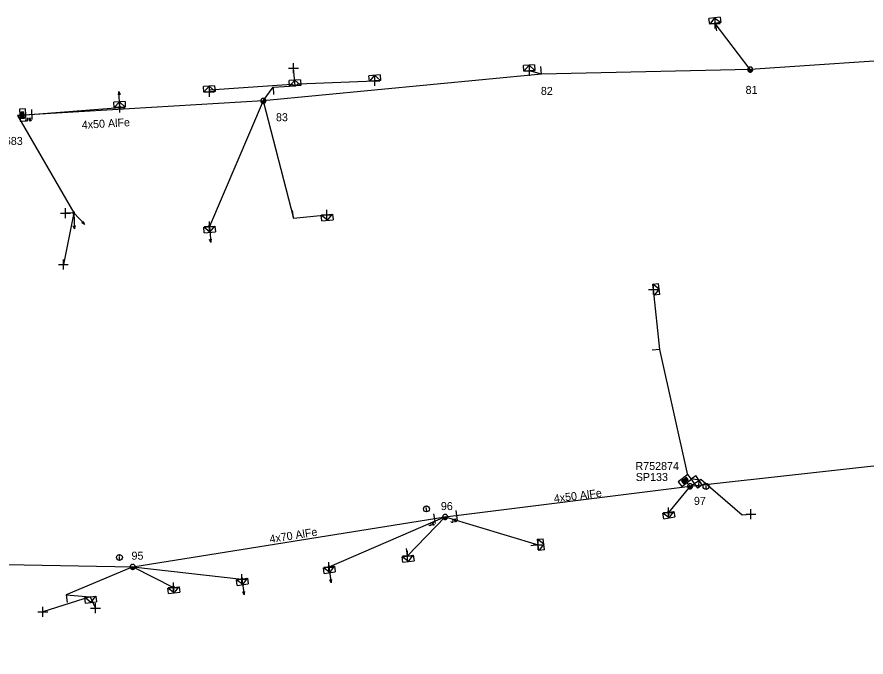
# Model space of a CAD drawing. Extents: x -544780 to -541582, y -1198995 to -1196551.
# Drawn here: x -541850 to -541744, y -1198813.8 to -1198734 of the extents above; entities that cross this region are included whole.
import ezdxf

# ---------------------------------------------------------------- set-up
doc = ezdxf.new("R2010")
doc.units = 0
for name, color, linetype in [('Vrstva 1', 7, 'Continuous'), ('Vrstva 10', 7, 'Continuous'), ('Vrstva 13', 7, 'Continuous'), ('Vrstva 14', 7, 'Continuous'), ('Vrstva 15', 7, 'Continuous'), ('Vrstva 18', 7, 'Continuous'), ('Vrstva 2', 7, 'Continuous'), ('Vrstva 28', 7, 'Continuous'), ('Vrstva 29', 7, 'Continuous'), ('Vrstva 30', 7, 'Continuous'), ('Vrstva 31', 7, 'Continuous'), ('Vrstva 34', 7, 'Continuous'), ('Vrstva 36', 7, 'Continuous'), ('Vrstva 52', 7, 'Continuous'), ('Vrstva 54', 7, 'Continuous'), ('Vrstva 59', 7, 'Continuous'), ('Vrstva 8', 7, 'Continuous'), ('Vrstva 9', 7, 'Continuous')]:
    doc.layers.add(name, color=color, linetype=linetype)

# ---------------------------------------------------------------- blocks, each defined once
blk = doc.blocks.new('NN440')
at = {"layer": 'Vrstva 2'}
for points in [[(0.63, 0), (0.63, 0.06), (0.62, 0.13), (0.6, 0.19), (0.58, 0.25), (0.55, 0.31), (0.51, 0.37), (0.47, 0.42), (0.42, 0.46), (0.37, 0.51), (0.32, 0.54), (0.26, 0.57), (0.2, 0.59), (0.13, 0.61), (0.07, 0.62), (0, 0.63), (-0.06, 0.62), (-0.13, 0.61), (-0.19, 0.59), (-0.26, 0.57), (-0.31, 0.54), (-0.37, 0.51), (-0.42, 0.46), (-0.47, 0.42), (-0.51, 0.37), (-0.54, 0.31), (-0.57, 0.25), (-0.6, 0.19), (-0.62, 0.13), (-0.63, 0.06), (-0.63, 0), (-0.63, -0.07), (-0.62, -0.14), (-0.6, -0.2), (-0.57, -0.26), (-0.54, -0.32), (-0.51, -0.37), (-0.47, -0.43), (-0.42, -0.47), (-0.37, -0.51), (-0.31, -0.55), (-0.26, -0.58), (-0.19, -0.6), (-0.13, -0.62), (-0.06, -0.63), (0, -0.63), (0.07, -0.63), (0.13, -0.62), (0.2, -0.6), (0.26, -0.58), (0.32, -0.55), (0.37, -0.51), (0.42, -0.47), (0.47, -0.43), (0.51, -0.37), (0.55, -0.32), (0.58, -0.26), (0.6, -0.2), (0.62, -0.14), (0.63, -0.07), (0.63, 0)], [(-0.63, 0), (0.63, 0)], [(-0.6, -0.18), (0.57, -0.18)], [(-0.51, -0.32), (0.5, -0.32)], [(-0.37, -0.47), (0.35, -0.47)]]:
    blk.add_lwpolyline(points, dxfattribs=at)
blk = doc.blocks.new('NN560')
at = {"layer": 'Vrstva 2'}
for points in [[(2, 0), (1.59, 0.14)], [(0, 0), (2, 0)], [(2, 0), (1.59, -0.13)]]:
    blk.add_lwpolyline(points, dxfattribs=at)
blk = doc.blocks.new('NN840')
at = {"layer": 'Vrstva 15'}
for points in [[(0, 0.62), (0, -0.63)], [(-0.75, -0.71), (-0.75, -0.66)], [(-0.73, -0.76), (-0.75, -0.71)], [(-0.66, -0.8), (-0.73, -0.76)], [(-0.63, -0.8), (-0.66, -0.8)], [(-0.56, -0.76), (-0.63, -0.8)], [(-0.54, -0.71), (-0.56, -0.76)], [(-0.54, -0.38), (-0.54, -0.71)], [(-0.33, -0.38), (-0.33, -0.8)], [(-0.33, -0.64), (-0.13, -0.38)], [(-0.26, -0.56), (-0.09, -0.8)]]:
    blk.add_lwpolyline(points, dxfattribs=at)
blk = doc.blocks.new('NN770')
at = {"layer": 'Vrstva 10'}
for p, q in [((0, 0.19), (0, 0.26)), ((0, -0.28), (0, 0.11))]:
    blk.add_line(p, q, dxfattribs=at)
blk.add_circle((0, -0.01), 0.375, dxfattribs=at)
blk = doc.blocks.new('NN800')
at = {"layer": 'Vrstva 1'}
for points in [[(-0.44, 0.44), (0.44, -0.44)], [(-0.44, -0.44), (0.44, 0.44)]]:
    blk.add_lwpolyline(points, dxfattribs=at)
blk = doc.blocks.new('NN620')
at = {"layer": 'Vrstva 8'}
for points in [[(0.75, 0), (-0.75, 0)], [(-0.75, 0), (-0.75, -0.75)], [(0.75, -0.75), (0.75, 0)], [(-0.75, -0.75), (0.75, -0.75)], [(0.37, -0.18), (-0.38, -0.18)], [(-0.38, -0.18), (-0.38, -0.56)], [(-0.38, -0.56), (0.37, -0.56)], [(0.32, -0.23), (-0.33, -0.23)], [(-0.33, -0.23), (-0.33, -0.51)], [(-0.33, -0.51), (0.32, -0.51)], [(0.27, -0.27), (-0.28, -0.27)], [(-0.28, -0.27), (-0.28, -0.46)], [(-0.28, -0.46), (0.27, -0.46)], [(0.23, -0.32), (-0.23, -0.32)], [(-0.23, -0.32), (-0.23, -0.42)], [(-0.23, -0.42), (0.23, -0.42)], [(-0.19, -0.37), (0.19, -0.37)], [(0.23, -0.42), (0.23, -0.32)], [(0.27, -0.46), (0.27, -0.27)], [(0.32, -0.51), (0.32, -0.23)], [(0.37, -0.56), (0.37, -0.18)]]:
    blk.add_lwpolyline(points, dxfattribs=at)
blk = doc.blocks.new('NN630')
at = {"layer": 'Vrstva 9'}
for points in [[(0, -0.7), (-0.7, 0)], [(-0.7, -0.7), (-0.7, 0), (0.7, 0), (0.7, -0.7)], [(-0.7, -0.7), (0.7, -0.7)], [(0, -0.7), (0.7, 0)]]:
    blk.add_lwpolyline(points, dxfattribs=at)
blk = doc.blocks.new('NN500')
at = {"layer": 'Vrstva 2'}
for points in [[(0, -0.24), (0.02, -0.23), (0.05, -0.23), (0.07, -0.22), (0.09, -0.22), (0.12, -0.2), (0.14, -0.19), (0.16, -0.18), (0.17, -0.16), (0.19, -0.14), (0.2, -0.12), (0.21, -0.1), (0.22, -0.07), (0.23, -0.05), (0.23, -0.02), (0.23, 0), (0.23, 0.02), (0.23, 0.05), (0.22, 0.07), (0.21, 0.1), (0.2, 0.12), (0.19, 0.14), (0.17, 0.16), (0.16, 0.17), (0.14, 0.19), (0.12, 0.2), (0.09, 0.21), (0.07, 0.22), (0.05, 0.23), (0.02, 0.23), (0, 0.23), (-0.03, 0.23), (-0.05, 0.23), (-0.07, 0.22), (-0.1, 0.21), (-0.12, 0.2), (-0.14, 0.19), (-0.16, 0.17), (-0.18, 0.16), (-0.19, 0.14), (-0.2, 0.12), (-0.22, 0.1), (-0.22, 0.07), (-0.23, 0.05), (-0.23, 0.02), (-0.24, 0), (-0.23, -0.02), (-0.23, -0.05), (-0.22, -0.07), (-0.22, -0.1), (-0.2, -0.12), (-0.19, -0.14), (-0.18, -0.16), (-0.16, -0.18), (-0.14, -0.19), (-0.12, -0.2), (-0.1, -0.22), (-0.07, -0.22), (-0.05, -0.23), (-0.03, -0.23), (0, -0.24)], [(0, -0.24), (0.02, -0.23), (0.05, -0.23), (0.07, -0.22), (0.09, -0.22), (0.12, -0.2), (0.14, -0.19), (0.16, -0.18), (0.17, -0.16), (0.19, -0.14), (0.2, -0.12), (0.21, -0.1), (0.22, -0.07), (0.23, -0.05), (0.23, -0.02), (0.23, 0), (0.23, 0.02), (0.23, 0.05), (0.22, 0.07), (0.21, 0.1), (0.2, 0.12), (0.19, 0.14), (0.17, 0.16), (0.16, 0.17), (0.14, 0.19), (0.12, 0.2), (0.09, 0.21), (0.07, 0.22), (0.05, 0.23), (0.02, 0.23), (0, 0.23), (-0.03, 0.23), (-0.05, 0.23), (-0.07, 0.22), (-0.1, 0.21), (-0.12, 0.2), (-0.14, 0.19), (-0.16, 0.17), (-0.18, 0.16), (-0.19, 0.14), (-0.2, 0.12), (-0.22, 0.1), (-0.22, 0.07), (-0.23, 0.05), (-0.23, 0.02), (-0.24, 0), (-0.23, -0.02), (-0.23, -0.05), (-0.22, -0.07), (-0.22, -0.1), (-0.2, -0.12), (-0.19, -0.14), (-0.18, -0.16), (-0.16, -0.18), (-0.14, -0.19), (-0.12, -0.2), (-0.1, -0.22), (-0.07, -0.22), (-0.05, -0.23), (-0.03, -0.23), (0, -0.24)], [(0, -0.21), (0.02, -0.2), (0.04, -0.2), (0.06, -0.2), (0.08, -0.19), (0.1, -0.18), (0.12, -0.17), (0.14, -0.15), (0.15, -0.14), (0.16, -0.12), (0.18, -0.1), (0.19, -0.08), (0.19, -0.06), (0.2, -0.04), (0.2, -0.02), (0.2, 0), (0.2, 0.02), (0.2, 0.04), (0.19, 0.06), (0.19, 0.08), (0.18, 0.1), (0.16, 0.12), (0.15, 0.14), (0.14, 0.15), (0.12, 0.17), (0.1, 0.18), (0.08, 0.19), (0.06, 0.19), (0.04, 0.2), (0.02, 0.2), (0, 0.2), (-0.02, 0.2), (-0.04, 0.2), (-0.06, 0.19), (-0.08, 0.19), (-0.1, 0.18), (-0.12, 0.17), (-0.14, 0.15), (-0.15, 0.14), (-0.17, 0.12), (-0.18, 0.1), (-0.19, 0.08), (-0.2, 0.06), (-0.2, 0.04), (-0.21, 0.02), (-0.21, 0), (-0.21, -0.02), (-0.2, -0.04), (-0.2, -0.06), (-0.19, -0.08), (-0.18, -0.1), (-0.17, -0.12), (-0.15, -0.14), (-0.14, -0.15), (-0.12, -0.17), (-0.1, -0.18), (-0.08, -0.19), (-0.06, -0.2), (-0.04, -0.2), (-0.02, -0.2), (0, -0.21)], [(0, -0.18), (0.02, -0.18), (0.04, -0.17), (0.05, -0.17), (0.07, -0.16), (0.09, -0.15), (0.1, -0.14), (0.12, -0.13), (0.13, -0.12), (0.14, -0.1), (0.15, -0.09), (0.16, -0.07), (0.17, -0.05), (0.17, -0.04), (0.17, -0.02), (0.17, 0), (0.17, 0.02), (0.17, 0.04), (0.17, 0.05), (0.16, 0.07), (0.15, 0.09), (0.14, 0.1), (0.13, 0.12), (0.12, 0.13), (0.1, 0.14), (0.09, 0.15), (0.07, 0.16), (0.05, 0.17), (0.04, 0.17), (0.02, 0.17), (0, 0.18), (-0.02, 0.17), (-0.04, 0.17), (-0.06, 0.17), (-0.07, 0.16), (-0.09, 0.15), (-0.1, 0.14), (-0.12, 0.13), (-0.13, 0.12), (-0.14, 0.1), (-0.15, 0.09), (-0.16, 0.07), (-0.17, 0.05), (-0.17, 0.04), (-0.18, 0.02), (-0.18, 0), (-0.18, -0.02), (-0.17, -0.04), (-0.17, -0.05), (-0.16, -0.07), (-0.15, -0.09), (-0.14, -0.1), (-0.13, -0.12), (-0.12, -0.13), (-0.1, -0.14), (-0.09, -0.15), (-0.07, -0.16), (-0.06, -0.17), (-0.04, -0.17), (-0.02, -0.18), (0, -0.18)], [(0, -0.15), (0.01, -0.15), (0.03, -0.14), (0.04, -0.14), (0.06, -0.13), (0.07, -0.13), (0.08, -0.12), (0.1, -0.11), (0.11, -0.1), (0.12, -0.09), (0.13, -0.07), (0.13, -0.06), (0.14, -0.05), (0.14, -0.03), (0.14, -0.02), (0.14, 0), (0.14, 0.01), (0.14, 0.03), (0.14, 0.04), (0.13, 0.06), (0.13, 0.07), (0.12, 0.09), (0.11, 0.1), (0.1, 0.11), (0.08, 0.12), (0.07, 0.13), (0.06, 0.13), (0.04, 0.14), (0.03, 0.14), (0.01, 0.14), (0, 0.15), (-0.02, 0.14), (-0.03, 0.14), (-0.05, 0.14), (-0.06, 0.13), (-0.07, 0.13), (-0.09, 0.12), (-0.1, 0.11), (-0.11, 0.1), (-0.12, 0.09), (-0.13, 0.07), (-0.13, 0.06), (-0.14, 0.04), (-0.14, 0.03), (-0.15, 0.01), (-0.15, 0), (-0.15, -0.02), (-0.14, -0.03), (-0.14, -0.05), (-0.13, -0.06), (-0.13, -0.07), (-0.12, -0.09), (-0.11, -0.1), (-0.1, -0.11), (-0.09, -0.12), (-0.07, -0.13), (-0.06, -0.13), (-0.05, -0.14), (-0.03, -0.14), (-0.02, -0.15), (0, -0.15)], [(0, -0.12), (0.01, -0.12), (0.02, -0.11), (0.03, -0.11), (0.05, -0.11), (0.06, -0.1), (0.07, -0.09), (0.08, -0.09), (0.09, -0.08), (0.09, -0.07), (0.1, -0.06), (0.11, -0.05), (0.11, -0.04), (0.11, -0.02), (0.11, -0.01), (0.12, 0), (0.11, 0.01), (0.11, 0.02), (0.11, 0.04), (0.11, 0.05), (0.1, 0.06), (0.09, 0.07), (0.09, 0.08), (0.08, 0.09), (0.07, 0.09), (0.06, 0.1), (0.05, 0.11), (0.03, 0.11), (0.02, 0.11), (0.01, 0.12), (0, 0.12), (-0.01, 0.12), (-0.03, 0.11), (-0.04, 0.11), (-0.05, 0.11), (-0.06, 0.1), (-0.07, 0.09), (-0.08, 0.09), (-0.09, 0.08), (-0.1, 0.07), (-0.1, 0.06), (-0.11, 0.05), (-0.11, 0.04), (-0.12, 0.02), (-0.12, 0.01), (-0.12, 0), (-0.12, -0.01), (-0.12, -0.02), (-0.11, -0.04), (-0.11, -0.05), (-0.1, -0.06), (-0.1, -0.07), (-0.09, -0.08), (-0.08, -0.09), (-0.07, -0.09), (-0.06, -0.1), (-0.05, -0.11), (-0.04, -0.11), (-0.03, -0.11), (-0.01, -0.12), (0, -0.12)], [(0, -0.09), (0.01, -0.09), (0.02, -0.09), (0.03, -0.08), (0.03, -0.08), (0.04, -0.08), (0.05, -0.07), (0.06, -0.07), (0.06, -0.06), (0.07, -0.05), (0.07, -0.04), (0.08, -0.04), (0.08, -0.03), (0.08, -0.02), (0.09, -0.01), (0.09, 0), (0.09, 0.01), (0.08, 0.02), (0.08, 0.03), (0.08, 0.03), (0.07, 0.04), (0.07, 0.05), (0.06, 0.06), (0.06, 0.06), (0.05, 0.07), (0.04, 0.07), (0.03, 0.08), (0.03, 0.08), (0.02, 0.08), (0.01, 0.09), (0, 0.09), (-0.01, 0.09), (-0.02, 0.08), (-0.03, 0.08), (-0.04, 0.08), (-0.04, 0.07), (-0.05, 0.07), (-0.06, 0.06), (-0.07, 0.06), (-0.07, 0.05), (-0.08, 0.04), (-0.08, 0.03), (-0.08, 0.03), (-0.09, 0.02), (-0.09, 0.01), (-0.09, 0), (-0.09, -0.01), (-0.09, -0.02), (-0.08, -0.03), (-0.08, -0.04), (-0.08, -0.04), (-0.07, -0.05), (-0.07, -0.06), (-0.06, -0.07), (-0.05, -0.07), (-0.04, -0.08), (-0.04, -0.08), (-0.03, -0.08), (-0.02, -0.09), (-0.01, -0.09), (0, -0.09)], [(0, -0.06), (0, -0.06), (0.01, -0.06), (0.02, -0.05), (0.02, -0.05), (0.03, -0.05), (0.03, -0.05), (0.04, -0.04), (0.04, -0.04), (0.05, -0.03), (0.05, -0.03), (0.05, -0.02), (0.05, -0.02), (0.05, -0.01), (0.06, -0.01), (0.06, 0), (0.06, 0.01), (0.05, 0.01), (0.05, 0.02), (0.05, 0.02), (0.05, 0.03), (0.05, 0.03), (0.04, 0.04), (0.04, 0.04), (0.03, 0.05), (0.03, 0.05), (0.02, 0.05), (0.02, 0.05), (0.01, 0.06), (0, 0.06), (0, 0.06), (-0.01, 0.06), (-0.01, 0.06), (-0.02, 0.05), (-0.02, 0.05), (-0.03, 0.05), (-0.03, 0.05), (-0.04, 0.04), (-0.04, 0.04), (-0.05, 0.03), (-0.05, 0.03), (-0.05, 0.02), (-0.06, 0.02), (-0.06, 0.01), (-0.06, 0.01), (-0.06, 0), (-0.06, -0.01), (-0.06, -0.01), (-0.06, -0.02), (-0.05, -0.02), (-0.05, -0.03), (-0.05, -0.03), (-0.04, -0.04), (-0.04, -0.04), (-0.03, -0.05), (-0.03, -0.05), (-0.02, -0.05), (-0.02, -0.05), (-0.01, -0.06), (-0.01, -0.06), (0, -0.06)], [(0, -0.03), (0, -0.03), (0, -0.03), (0.01, -0.03), (0.01, -0.03), (0.01, -0.02), (0.02, -0.02), (0.02, -0.02), (0.02, -0.02), (0.02, -0.02), (0.02, -0.01), (0.02, -0.01), (0.03, -0.01), (0.03, -0.01), (0.03, 0), (0.03, 0), (0.03, 0), (0.03, 0.01), (0.03, 0.01), (0.02, 0.01), (0.02, 0.01), (0.02, 0.02), (0.02, 0.02), (0.02, 0.02), (0.02, 0.02), (0.01, 0.02), (0.01, 0.02), (0.01, 0.03), (0, 0.03), (0, 0.03), (0, 0.03), (0, 0.03), (-0.01, 0.03), (-0.01, 0.03), (-0.01, 0.02), (-0.02, 0.02), (-0.02, 0.02), (-0.02, 0.02), (-0.02, 0.02), (-0.02, 0.02), (-0.03, 0.01), (-0.03, 0.01), (-0.03, 0.01), (-0.03, 0.01), (-0.03, 0), (-0.03, 0), (-0.03, 0), (-0.03, -0.01), (-0.03, -0.01), (-0.03, -0.01), (-0.03, -0.01), (-0.02, -0.02), (-0.02, -0.02), (-0.02, -0.02), (-0.02, -0.02), (-0.02, -0.02), (-0.01, -0.03), (-0.01, -0.03), (-0.01, -0.03), (0, -0.03), (0, -0.03)], [(0.23, 0), (0.7, 0)]]:
    blk.add_lwpolyline(points, dxfattribs=at)
blk = doc.blocks.new('NN510')
at = {"layer": 'Vrstva 2'}
blk.add_lwpolyline([(0, 0), (0, 0.94)], dxfattribs=at)

msp = doc.modelspace()

# ---------------------------------------------------------------- linework, layer by layer
at = {"layer": 'Vrstva 1'}
for points in [[(-541675.9, -1198734.63), (-541707.69, -1198736.78), (-541736.18, -1198739.01), (-541758.43, -1198740.53), (-541784.49, -1198741.09), (-541819.23, -1198744.44), (-541849.91, -1198746.25)], [(-541765.94, -1198792.53), (-541736.26, -1198789.23)], [(-541796.52, -1198796.35), (-541765.94, -1198792.53)], [(-541970.92, -1198813.83), (-541931.95, -1198805.83), (-541907.49, -1198801.08), (-541871.72, -1198801.93), (-541835.54, -1198802.58), (-541796.52, -1198796.35)]]:
    msp.add_lwpolyline(points, dxfattribs=at)
at = {"layer": 'Vrstva 52'}
for points in [[(-541765.94, -1198792.53), (-541765.39, -1198792.18), (-541764.6, -1198791.63), (-541759.44, -1198796.1), (-541758.36, -1198796)], [(-541765.94, -1198792.53), (-541766.36, -1198792.1)]]:
    msp.add_lwpolyline(points, dxfattribs=at)
at = {"layer": 'Vrstva 54'}
for points in [[(-541758.43, -1198740.53), (-541762.79, -1198734.77)], [(-541784.49, -1198741.09), (-541786.01, -1198740.7)], [(-541819.23, -1198744.44), (-541815.48, -1198759.06), (-541811.29, -1198758.64)], [(-541849.91, -1198746.25), (-541837.16, -1198745.25)], [(-541849.91, -1198746.25), (-541842.91, -1198758.42)], [(-541766.22, -1198791.16), (-541769.73, -1198775.46), (-541770.5, -1198767.99)], [(-541765.94, -1198792.53), (-541768.65, -1198795.78)], [(-541796.52, -1198796.35), (-541811.04, -1198802.61)], [(-541796.52, -1198796.35), (-541801.21, -1198801.22)], [(-541796.52, -1198796.35), (-541784.91, -1198799.84)], [(-541835.54, -1198802.58), (-541830.45, -1198805.14)], [(-541835.54, -1198802.58), (-541821.9, -1198804.11)]]:
    msp.add_lwpolyline(points, dxfattribs=at)
at = {"layer": 'Vrstva 59'}
for points in [[(-541815.25, -1198742.56), (-541815.46, -1198740.35)], [(-541815.25, -1198742.56), (-541815.65, -1198742.41), (-541825.95, -1198743.11), (-541825.95, -1198743.31)], [(-541815.25, -1198742.56), (-541814.84, -1198742.3), (-541805.29, -1198741.95)], [(-541842.91, -1198758.42), (-541844.2, -1198764.87)], [(-541842.91, -1198758.42), (-541843.93, -1198758.47)], [(-541840.84, -1198806.34), (-541846.75, -1198808.21)], [(-541840.83, -1198806.34), (-541840.19, -1198807.73)]]:
    msp.add_lwpolyline(points, dxfattribs=at)
at = {"layer": 'Vrstva 8'}
for points in [[(-541819.23, -1198744.44), (-541818, -1198742.72), (-541815.25, -1198742.56)], [(-541819.23, -1198744.44), (-541825.97, -1198760.13)], [(-541835.54, -1198802.58), (-541843.85, -1198806.08), (-541840.83, -1198806.34)]]:
    msp.add_lwpolyline(points, dxfattribs=at)

# ---------------------------------------------------------------- block references
at = {"layer": 'Vrstva 13'}
for name, p, rotation in [('NN510', (-541762.79, -1198734.77), -171.74354720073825), ('NN510', (-541784.5, -1198741.09), 3.4632444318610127), ('NN510', (-541818, -1198742.72), -176.59971659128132), ('NN560', (-541837.16, -1198745.25), 92.677924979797), ('NN560', (-541842.91, -1198758.42), -87.45348339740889), ('NN560', (-541842.91, -1198758.42), -46.228522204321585), ('NN510', (-541815.48, -1198759.06), 5.842730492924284), ('NN560', (-541825.97, -1198760.13), -84.5936389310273), ('NN510', (-541769.73, -1198775.46), 95.85318054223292), ('NN510', (-541784.9, -1198799.84), 96.19973336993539), ('NN510', (-541801.21, -1198801.22), 7.994863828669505), ('NN560', (-541811.04, -1198802.61), -81.79409448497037), ('NN560', (-541821.9, -1198804.11), -81.82554719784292), ('NN510', (-541843.85, -1198806.08), -172.85427826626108)]:
    msp.add_blockref(name, p, dxfattribs=dict(at, rotation=rotation))
for name, p, xscale, yscale, rotation in [('NN440', (-541758.43, -1198740.53), 0.5, 0.5, 3.908066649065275), ('NN500', (-541837.16, -1198745.25), 0.49999999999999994, 0.5, 92.67799999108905), ('NN440', (-541819.23, -1198744.44), 0.5, 0.49999999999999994, 5.508825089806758), ('NN500', (-541842.91, -1198758.42), 0.5, 0.5, -87.45299995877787), ('NN500', (-541825.97, -1198760.13), 0.49999999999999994, 0.4999999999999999, -84.59400000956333), ('NN440', (-541765.94, -1198792.53), 0.5, 0.49999999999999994, 7.120405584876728), ('NN500', (-541768.65, -1198795.78), 0.49999999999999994, 0.5000000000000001, -80.82400001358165), ('NN440', (-541796.52, -1198796.35), 0.5, 0.5, 9.071377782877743), ('NN440', (-541835.54, -1198802.58), 0.5, 0.5, -1.0292501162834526), ('NN500', (-541811.04, -1198802.61), 0.5, 0.5000000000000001, -81.79400005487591), ('NN500', (-541821.9, -1198804.11), 0.49999999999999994, 0.5, -81.82600000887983), ('NN500', (-541830.45, -1198805.14), 0.49999999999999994, 0.5000000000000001, -83.40599994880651)]:
    msp.add_blockref(name, p, dxfattribs=dict(at, xscale=xscale, yscale=yscale, rotation=rotation))
at = {"layer": 'Vrstva 18'}
for p, rotation in [((-541848.16, -1198746.15), 3.377727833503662), ((-541795.1, -1198796.17), 7.120405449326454), ((-541797.88, -1198796.57), 9.071377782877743)]:
    msp.add_blockref('NN840', p, dxfattribs=dict(at, rotation=rotation))
at = {"layer": 'Vrstva 28'}
for p, rotation in [((-541849.65, -1198746.24), 93.37800001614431), ((-541766.36, -1198792.1), -142.82419552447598)]:
    msp.add_blockref('NN620', p, dxfattribs=dict(at, rotation=rotation))
at = {"layer": 'Vrstva 31'}
for p, rotation in [((-541762.79, -1198734.77), -171.74354720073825), ((-541786.01, -1198740.7), -176.536755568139), ((-541815.25, -1198742.56), -176.59971659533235), ((-541805.29, -1198741.95), -176.30501106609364), ((-541825.95, -1198743.31), -175.6817777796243), ((-541837.16, -1198745.25), -177.32207494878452), ((-541811.29, -1198758.64), 5.842730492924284), ((-541825.97, -1198760.13), 5.406361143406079), ((-541770.5, -1198767.99), 95.85318054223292), ((-541765.39, -1198792.18), 125.53312496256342), ((-541768.65, -1198795.78), 9.175694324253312), ((-541784.9, -1198799.84), 96.19973336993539), ((-541801.2, -1198801.22), 7.994863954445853), ((-541811.04, -1198802.61), 8.205905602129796), ((-541821.9, -1198804.11), 8.174452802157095), ((-541830.45, -1198805.14), 6.5938111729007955), ((-541840.84, -1198806.34), 7.062602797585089)]:
    msp.add_blockref('NN630', p, dxfattribs=dict(at, rotation=rotation))
at = {"layer": 'Vrstva 34'}
for p, rotation in [((-541762.79, -1198734.77), 44.99999995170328), ((-541815.46, -1198740.35), 45), ((-541786.01, -1198740.7), 45), ((-541805.29, -1198741.95), 45), ((-541825.95, -1198743.31), 45), ((-541837.16, -1198745.25), 45), ((-541843.93, -1198758.47), 44.99999995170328), ((-541811.29, -1198758.64), 45.00000009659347), ((-541825.97, -1198760.13), 44.99999995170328), ((-541844.2, -1198764.87), 45), ((-541770.5, -1198767.99), 45), ((-541768.65, -1198795.78), 45), ((-541758.36, -1198796), 45), ((-541784.91, -1198799.84), 45), ((-541801.21, -1198801.22), 44.99999995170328), ((-541811.04, -1198802.61), 45), ((-541821.9, -1198804.11), 45), ((-541830.45, -1198805.14), 44.99999995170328), ((-541846.75, -1198808.21), 44.99999995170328), ((-541840.19, -1198807.73), 44.99999995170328)]:
    msp.add_blockref('NN800', p, dxfattribs=dict(at, rotation=rotation))
at = {"layer": 'Vrstva 36'}
msp.add_blockref('NN770', (-541763.94, -1198792.53), dxfattribs=at)
for p, rotation in [((-541798.86, -1198795.34), 9.07137791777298), ((-541837.19, -1198801.4), -1.0292499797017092)]:
    msp.add_blockref('NN770', p, dxfattribs=dict(at, rotation=rotation))

# ---------------------------------------------------------------- texts
at = {"layer": 'Vrstva 14'}
for s, p in [('82', (-541784.57, -1198743.7)), ('81', (-541759.01, -1198743.57)), ('83', (-541817.65, -1198746.98)), ('96', (-541797.06, -1198795.5)), ('97', (-541765.46, -1198794.85)), ('95', (-541835.69, -1198801.69))]:
    msp.add_text(s, height=1, dxfattribs=at).set_placement(p)
at = {"layer": 'Vrstva 2'}
for s, rotation, p in [('4x50 AlFe', 3.376, (-541841.87, -1198747.94)), ('4x50 AlFe', 7.12, (-541782.89, -1198794.57)), ('4x70 AlFe', 9.071, (-541818.37, -1198799.62))]:
    msp.add_text(s, height=1, rotation=rotation, dxfattribs=at).set_placement(p)
at = {"layer": 'Vrstva 29'}
for s, p in [('R223683', (-541854.7, -1198749.94)), ('R752874', (-541772.76, -1198790.5))]:
    msp.add_text(s, height=1, dxfattribs=at).set_placement(p)
at = {"layer": 'Vrstva 30'}
msp.add_text('SP133', height=1, dxfattribs=at).set_placement((-541772.72, -1198791.87))

doc.saveas('drawing.dxf')
